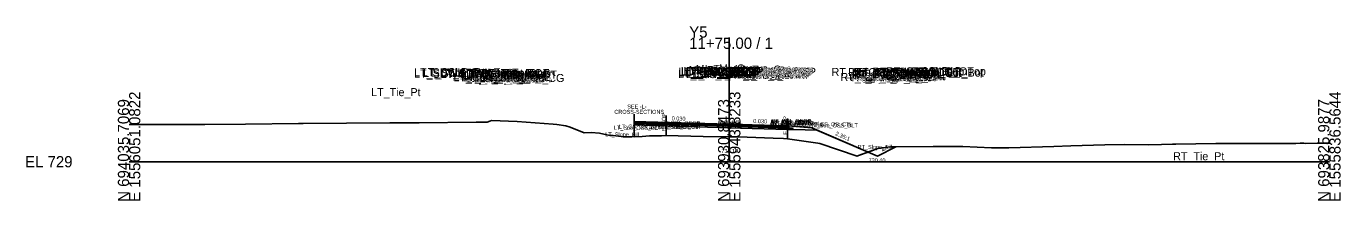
# Model space of a CAD drawing. Extents: x -26 to 4229, y -10 to 9523.
# Drawn here: x -25.7 to 302.8, y 2990.3 to 3033.7 of the extents above; entities that cross this region are included whole.
import ezdxf

# ---------------------------------------------------------------- set-up
doc = ezdxf.new("R2010")
doc.units = 0
for name, color, linetype in [('Default', 7, 'Continuous'), ('Exist Cross Section Cell', 7, 'Continuous'), ('Exist XS Center Line Elevation Label', 7, 'Continuous'), ('Exist XS Ground Line', 7, 'Continuous'), ('Old_Level_63', 7, 'Continuous'), ('Prop CMT Pvmt Course 1', 7, 'Continuous'), ('Prop CMT Pvmt Course 2', 7, 'Continuous'), ('Prop CMT Pvmt Course 3', 7, 'Continuous'), ('Prop CMT Pvmt Surface', 7, 'Continuous'), ('Prop CMT Pvmt Surface Shoulder', 7, 'Continuous'), ('Prop CMT Shld Paved Course 1', 7, 'Continuous'), ('Prop CMT Shld Paved Course 2', 7, 'Continuous'), ('Prop CMT Shld Paved Course 3', 7, 'Continuous'), ('Prop CMT Slope Grass', 7, 'Continuous'), ('Prop CMT Subgrade Earthwork', 7, 'Continuous'), ('Prop XS Earthwork Shape', 7, 'Continuous'), ('Prop XS Label Text', 7, 'Continuous'), ('Prop XSC Text', 7, 'Continuous'), ('Scratch_Level_1', 7, 'Continuous')]:
    doc.layers.add(name, color=color, linetype=linetype)

msp = doc.modelspace()

# ---------------------------------------------------------------- linework, layer by layer
at = {"layer": 'Exist Cross Section Cell'}
for p, q in [((150, 3000), (150, 3030.92)), ((0, 3000), (150, 3000)), ((150, 3000), (300, 3000))]:
    msp.add_line(p, q, dxfattribs=at)
at = {"layer": 'Exist XS Ground Line'}
msp.add_lwpolyline([(0, 3009.3), (10.46, 3009.24), (18.9, 3009.3), (29.08, 3009.39), (42.37, 3009.54), (42.78, 3009.54), (43.5, 3009.55), (65.19, 3009.66), (72.53, 3009.71), (86.79, 3009.89), (87.86, 3009.87), (89.52, 3009.87), (90.15, 3010.14), (90.57, 3010.31), (96.99, 3010.04), (105.96, 3009.38), (106.91, 3009.24), (109.18, 3008.91), (110.26, 3008.58), (113.74, 3007.2), (115.5, 3007.28), (117.56, 3007.12), (120.19, 3006.52), (121, 3006.5), (123.63, 3006.22), (125.27, 3006.22), (128.22, 3006.27), (130.08, 3006.42), (133.09, 3006.47), (134.18, 3006.51), (143.53, 3006.26), (150, 3006.19), (152.31, 3006.16), (160.95, 3005.86), (163.58, 3005.77), (164.6, 3005.74), (172.13, 3004.65), (172.67, 3004.56), (181.95, 3001.42), (182.32, 3001.51), (187.13, 3003.3), (190.31, 3003.7), (200.99, 3003.81), (208.36, 3003.83), (215.53, 3003.49), (217.2, 3003.45), (219.9, 3003.47), (231.12, 3003.8), (235.36, 3003.95), (243.86, 3004.17), (248.79, 3004.29), (254.74, 3004.22), (258.08, 3004.28), (260.76, 3004.38), (261.6, 3004.4), (271.63, 3004.55), (272.83, 3004.56), (281.08, 3004.5), (281.68, 3004.5), (291.59, 3004.53), (292.69, 3004.64), (293.66, 3004.59), (294.1, 3004.56), (296.93, 3004.63), (298.04, 3004.64), (300, 3004.62)], dxfattribs=at)
at = {"layer": 'Old_Level_63'}
msp.add_line((126.26, 3011.83), (126.26, 3007.65), dxfattribs=at)
at = {"layer": 'Prop CMT Pvmt Course 1'}
for points in [[(149.78, 3009.34), (126.26, 3010.05)], [(126.26, 3010.05), (126.26, 3009.8)], [(126.26, 3009.8), (149.78, 3009.09)], [(149.78, 3009.09), (149.78, 3009.34)], [(149.78, 3009.34), (164.68, 3008.9)], [(149.78, 3009.09), (149.78, 3009.34)], [(164.68, 3008.65), (149.78, 3009.09)], [(164.68, 3008.9), (164.68, 3008.65)]]:
    msp.add_lwpolyline(points, dxfattribs=at)
at = {"layer": 'Prop CMT Pvmt Course 2'}
for points in [[(149.78, 3009.09), (126.26, 3009.8)], [(126.26, 3009.8), (126.26, 3009.55)], [(126.26, 3009.55), (149.78, 3008.84)], [(149.78, 3008.84), (149.78, 3009.09)], [(149.78, 3008.84), (149.78, 3009.09)], [(149.78, 3009.09), (164.68, 3008.65)], [(164.68, 3008.4), (149.78, 3008.84)], [(164.68, 3008.65), (164.68, 3008.4)]]:
    msp.add_lwpolyline(points, dxfattribs=at)
at = {"layer": 'Prop CMT Pvmt Course 3'}
for points in [[(149.78, 3008.84), (126.26, 3009.55)], [(126.26, 3009.55), (126.26, 3009.18)], [(126.26, 3009.18), (149.78, 3008.47)], [(149.78, 3008.47), (149.78, 3008.84)], [(149.78, 3008.84), (164.68, 3008.4)], [(149.78, 3008.47), (149.78, 3008.84)], [(164.68, 3008.02), (149.78, 3008.47)], [(164.68, 3008.4), (164.68, 3008.02)]]:
    msp.add_lwpolyline(points, dxfattribs=at)
at = {"layer": 'Prop CMT Pvmt Surface'}
for points in [[(149.78, 3009.34), (126.26, 3010.05)], [(149.78, 3009.34), (164.68, 3008.9)]]:
    msp.add_lwpolyline(points, dxfattribs=at)
at = {"layer": 'Prop CMT Pvmt Surface Shoulder'}
for points in [[(126.26, 3010.05), (126.26, 3010.05)], [(164.68, 3008.9), (164.68, 3008.9)]]:
    msp.add_lwpolyline(points, dxfattribs=at)
at = {"layer": 'Prop CMT Shld Paved Course 1'}
for points in [[(126.26, 3010.05), (126.26, 3010.05)], [(126.26, 3009.8), (126.26, 3010.05)], [(164.68, 3008.9), (164.68, 3008.9)], [(164.68, 3008.9), (164.93, 3008.64)], [(164.68, 3008.65), (164.68, 3008.9)], [(164.93, 3008.64), (164.68, 3008.65)]]:
    msp.add_lwpolyline(points, dxfattribs=at)
at = {"layer": 'Prop CMT Shld Paved Course 2'}
for points in [[(126.26, 3009.55), (126.26, 3009.8)], [(164.68, 3008.65), (164.93, 3008.64), (165.19, 3008.39)], [(164.68, 3008.4), (164.68, 3008.65)], [(165.19, 3008.39), (164.68, 3008.4)]]:
    msp.add_lwpolyline(points, dxfattribs=at)
at = {"layer": 'Prop CMT Shld Paved Course 3'}
for points in [[(126.26, 3009.18), (126.26, 3009.55)], [(164.68, 3008.4), (165.19, 3008.39), (165.69, 3008.38), (166.07, 3007.99)], [(164.68, 3008.02), (164.68, 3008.4)], [(166.07, 3007.99), (164.68, 3008.02)]]:
    msp.add_lwpolyline(points, dxfattribs=at)
at = {"layer": 'Prop CMT Slope Grass'}
msp.add_line((191.68, 3003.71), (187.06, 3001.4), dxfattribs=at)
msp.add_lwpolyline([(164.68, 3008.9), (170.68, 3008.42), (187.06, 3001.4)], dxfattribs=at)
at = {"layer": 'Prop CMT Subgrade Earthwork'}
msp.add_line((126.26, 3010.05), (126.26, 3006.24), dxfattribs=at)
for points in [[(149.78, 3008.47), (126.26, 3009.18)], [(149.78, 3008.47), (164.68, 3008.02)], [(164.68, 3008.02), (166.07, 3007.99)], [(171.94, 3007.88), (166.07, 3007.99)]]:
    msp.add_lwpolyline(points, dxfattribs=at)
at = {"layer": 'Prop XS Earthwork Shape'}
for points in [[(171.94, 3007.88), (166.07, 3007.99), (164.68, 3008.02), (149.78, 3008.47), (126.26, 3009.18), (126.26, 3006.24), (128.22, 3006.27), (130.08, 3006.42), (133.09, 3006.47), (134.18, 3006.51), (143.53, 3006.26), (150, 3006.19), (152.31, 3006.16), (160.95, 3005.86), (163.58, 3005.77), (164.6, 3005.74), (172.13, 3004.65), (172.67, 3004.56), (181.95, 3001.42), (182.32, 3001.51), (184.72, 3002.4)], [(184.72, 3002.4), (187.13, 3003.3), (190.31, 3003.7), (190.34, 3003.7), (191.68, 3003.71), (187.06, 3001.4)]]:
    msp.add_lwpolyline(points, close=True, dxfattribs=at)
at = {"layer": 'Prop XS Label Text'}
for p, q in [((134.26, 3011.51), (134.26, 3006.51)), ((164.6, 3010.74), (164.6, 3005.74))]:
    msp.add_line(p, q, dxfattribs=at)

# ---------------------------------------------------------------- texts
at = {"layer": 'Default'}
for s, height, p in [('LT_SDWK_Out_Top', 2, (71.24, 3021.29)), ('LT_SDWK_Out_Bot', 2, (71.27, 3020.96)), ('LT_CSLP_Pnt', 2, (73.17, 3021.32)), ('LT_Sub_Trench_Out_DLT', 2, (73.49, 3021.12)), ('LT_SDWK_In_Top', 2, (77.86, 3021.19)), ('LT_SDWK_In_Bot', 2, (77.89, 3020.86)), ('LT_CG_Top_Face', 2, (82.76, 3021.08)), ('LT_CG_Top_BOC', 2, (83.28, 3021.08)), ('LT_CG_Top_Gut', 2, (83.74, 3020.58)), ('LT_PV1_OEOT', 2, (88.24, 3020.7)), ('LT_Sub_OEEOP', 2, (137.22, 3020.83)), ('LT_PV2_OEEOP', 2, (137.32, 3021.46)), ('LT_PV3_OEEOP', 2, (137.32, 3021.21)), ('LT_PV1_OEEOP', 2, (137.88, 3021.58)), ('LT_PV2_IEEOP', 2, (137.96, 3021.46)), ('LT_PV1_IEEOP', 2, (138.53, 3021.58)), ('LT_PV2_PGL1', 2, (138.89, 3021.46)), ('LT_PV3_PGL1', 2, (138.89, 3021.21)), ('LT_PV2_PGL', 2, (139.22, 3021.46)), ('LT_PV4_PGL', 2, (139.22, 3020.83)), ('LT_PV1_PGL', 2, (139.79, 3021.71)), ('MI_Face In', 2, (139.91, 3021.87)), ('MI_Bot In', 2, (140.89, 3021.71)), ('MI_Top In', 2, (141.62, 3022.12)), ('MI_Crown', 2, (147.45, 3022.24)), ('RT_Sub_OEEOP', 2, (149.92, 3020.66)), ('RT_PV2_OEEOP', 2, (150.01, 3021.28)), ('RT_PV3_OEEOP', 2, (150.01, 3021.03)), ('RT_PV1_OEEOP', 2, (150.58, 3021.41)), ('RT_PV2_IEEOP', 2, (150.66, 3021.28)), ('MI_Face Out', 2, (151.01, 3021.7)), ('MI_Top Out', 2, (151.22, 3021.95)), ('RT_PV1_IEEOP', 2, (151.22, 3021.41)), ('RT_PV2_PGL1', 2, (151.58, 3021.28)), ('RT_PV3_PGL1', 2, (151.58, 3021.03)), ('RT_PV2_PGL', 2, (151.92, 3021.28)), ('RT_PV4_PGL', 2, (151.92, 3020.66)), ('MI_Bot Out', 2, (152.01, 3021.53)), ('RT_PV1_PGL', 2, (152.48, 3021.53)), ('RT_Sub_Trench_Out_DLT', 2, (175.59, 3021.36)), ('RT_CG_Top_Face', 2, (179.71, 3021.32)), ('RT_PV2_OEOT', 2, (180.63, 3020.69)), ('RT_CG_Top_Gut', 2, (180.69, 3020.82)), ('RT_PV1_OEOT', 2, (181.19, 3020.94)), ('RT_CG_Top_BOC', 2, (181.24, 3021.32)), ('RT_SDWK_In_Top', 2, (185.81, 3021.43)), ('RT_SDWK_In_Bot', 2, (185.84, 3021.1)), ('RT_SDWK_Out_Top', 2, (189.19, 3021.53)), ('RT_SDWK_Out_Bot', 2, (189.22, 3021.2)), ('RT_Shld_O', 2, (195.54, 3021.52)), ('CSLP_Pnt', 2, (197.87, 3021.56)), ('LT_CG1_Shelf_Out', 2, (81.05, 3020.05)), ('LT_CG_Bot_BOC', 2, (83.31, 3020.06)), ('LT_Sub_OEOP', 2, (84.36, 3019.8)), ('LT_Sub_OEOT_CG', 2, (84.87, 3019.86)), ('LT_CG_Bot_IE', 2, (87.41, 3020.11)), ('LT_Sub_OEOT', 2, (87.58, 3019.82)), ('LT_PV2_OEOT', 2, (87.67, 3020.45)), ('LT_PV3_OEOT', 2, (87.67, 3020.2)), ('RT_Sub_OEOT_CG', 2, (177.82, 3020.1)), ('RT_CG1_Shelf_Out', 2, (180, 3020.29)), ('RT_CG_Bot_IE', 2, (180.37, 3020.35)), ('RT_Sub_OEOT', 2, (180.53, 3020.06)), ('RT_PV3_OEOT', 2, (180.63, 3020.44)), ('RT_CG_Bot_BOC', 2, (181.27, 3020.3)), ('RT_Sub_OEOP', 2, (183.82, 3020.04)), ('LT_Tie_Pt', 2, (60.51, 3016.34)), ('-', 0.0001, (0, 3000)), ('-', 0.0001, (0, 3000)), ('-', 0.0001, (0, 3000)), ('-', 0.0001, (0, 3000)), ('-', 0.0001, (0, 3000)), ('-', 0.0001, (0, 3000)), ('-', 0.0001, (0, 3000)), ('-', 0.0001, (0, 3000)), ('-', 0.0001, (0, 3000)), ('-', 0.0001, (0, 3000)), ('RT_Tie_Pt', 2, (260.97, 3000.37))]:
    msp.add_text(s, height=height, dxfattribs=at).set_placement(p)
at = {"layer": 'Exist Cross Section Cell'}
for s, p in [('Y5', (140, 3030.92)), ('11+75.00 / 1', (140, 3028.12)), ('EL 729', (-26, 2998.6))]:
    msp.add_text(s, height=2.8, dxfattribs=at).set_placement(p)
for s, p in [('E 1556051.0822', (2.8, 2990)), ('E 1555943.8233', (152.8, 2990)), ('E 1555836.5644', (302.8, 2990)), ('N 694035.7069', (0, 2990)), ('N 693930.8473', (150, 2990)), ('N 693825.9877', (300, 2990))]:
    msp.add_text(s, height=2.8, rotation=90, dxfattribs=at).set_placement(p)
at = {"layer": 'Exist XS Center Line Elevation Label'}
msp.add_text('735.19', height=1, dxfattribs=at).set_placement((148.03, 3002.19))
at = {"layer": 'Prop XS Label Text'}
for p in [(134.16, 3007.53), (164.5, 3006.75)]:
    msp.add_text('E. EOP', height=1, rotation=90, dxfattribs=at).set_placement(p)
at = {"layer": 'Prop XSC Text'}
for s, p in [('CROSS-SECTIONS', (121.29, 3011.93)), ('SEE -L-', (124.52, 3013.24)), ('730.40', (184.84, 2999.88))]:
    msp.add_text(s, height=1, dxfattribs=at).set_placement(p)
for s, rotation, p in [('0.030', 358.2816, (135.6, 3010.3)), ('0.030', 358.2816, (155.99, 3009.64)), ('2.35:1', 336.6636, (176.43, 3006.66)), ('2:1', 26.5651, (188.26, 3002.56))]:
    msp.add_text(s, height=1, rotation=rotation, dxfattribs=at).set_placement(p)
at = {"layer": 'Scratch_Level_1'}
for s, p in [('LT_PS3_Shelf_Out', (130.73, 3008.56)), ('LT_PS3_OEOP', (132.37, 3008.57)), ('LT_PS2_OEOP', (132.63, 3008.82)), ('LT_PV2_OEOT', (132.85, 3008.83)), ('LT_PV3_OEOT', (132.85, 3008.58)), ('LT_PV1_OEOT', (132.97, 3009.08)), ('LT_PS1_OEOP', (133.01, 3009.08)), ('Sub_PGL', (147.15, 3008.48)), ('PV2_PGL', (147.13, 3009.1)), ('PV3_PGL', (147.13, 3008.85)), ('PV1_PGL', (147.25, 3009.35)), ('RT_Sub_Trench_Out', (160.12, 3008.75)), ('RT_PS3_Shelf_Out', (160.29, 3009.13)), ('RT_PV2_OEOT', (160.37, 3009.4)), ('RT_PV3_OEOT', (160.37, 3009.15)), ('RT_Sub_OEOT', (160.39, 3008.77)), ('RT_PV1_OEOT', (160.49, 3009.65)), ('RT_PS1_OEOP', (160.53, 3009.65)), ('RT_PS2_OEOP', (160.66, 3009.39)), ('RT_PS3_OEOP', (160.92, 3009.14)), ('RT_Sub_OSS_DLT', (170.01, 3008.56)), ('RT_GS_OS_CTL', (170.05, 3008.85)), ('LT_Slope_Fill', (119.01, 3006.29)), ('LT_Sub_OSS_DLT', (121.17, 3007.98)), ('LT_GS_OS_CTL', (122.37, 3008.27)), ('LT_Sub_Trench_Out', (129.8, 3008.18)), ('LT_Sub_OEOT', (132.87, 3008.2)), ('RT_Slope_Fill', (182.09, 3003.18))]:
    msp.add_text(s, height=1, rotation=359.8763, dxfattribs=at).set_placement(p)

doc.saveas('drawing.dxf')
